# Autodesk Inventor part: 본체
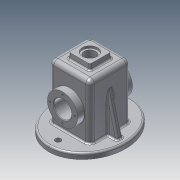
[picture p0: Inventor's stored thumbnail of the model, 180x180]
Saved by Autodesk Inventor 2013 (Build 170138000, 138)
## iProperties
Created: 2017-07
Part Number: 본체
Material: 알루미늄 6061
Document SubType Name: Modeling
Designer: Administrator
Density: 1 g/cm^3
Author: Administrator
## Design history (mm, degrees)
sketch "스케치1"
  geometry: L1 (-37, -55)-(37, -55); L2 (37, -55)-(37, 55); L3 (37, 55)-(-37, 55); L4 (-37, 55)-(-37, -55); L5 (-37, -55)-(37, 55); L6 (37, -55)-(-37, 55); 3 further points
  constraints: 12 end point, 3 midpoint, 2 parallel, 1 coincident, 1 horizontal, 1 perpendicular
  dimensions: "d0" = 74 distance of L3.end L2.end; "d1" = 110 distance of L2.end L1.end
extrude "돌출1" new body sketch "스케치1" stored distance "d2" = 74; taper "d3" = 0 deg
fillet "모깎기1" dims "d4" = 8
fillet "모깎기2" dims "d5" = 8
feature "쉘1" dims "d6" = 5
sketch "스케치2"
  geometry: L1 (-55, 32)-(47, 32) reference; L2 (-55, -29)-(-55, 29) reference; L3 (-55, 29)-(-55, 32) reference; L4 (-55, 37)-(47, 37) reference; L5 (-55, 0)-(0, 0); L6 (0, 0)-(0, 37); L7 (34.5, 32)-(27.5, 25); L8 (27.5, 25)-(0, 25); L9 (0, 32)-(34.5, 32); L10 (0, 32)-(0, 25); A1 r 8 centre (47, 29) between (55, 29) and (47, 37) reference; 1 further point
  constraints: 12 end point, 5 point on line, 2 perpendicular, 1 collinear, 1 midpoint, 1 parallel
  dimensions: "d10" = 55 distance of L5.start L5.end; "d11" = 7 distance between parallel lines of L8 L9; "d12" = 135 deg angle of L8 L7; "d13" = 55 diameter of L7.end L6
revolve "회전1" sketch "스케치2" stored, may be unused: angle "d14" = 90 deg
fillet "모깎기5" dims "d45" = 0.5
sketch "스케치7"
  geometry: C1 r 27.5 at (0, 0); 1 further point
  constraints: 1 centre point, 1 coincident
  dimensions: "d46" = 55 diameter of C1
extrude "돌출5" join sketch "스케치7" distance "d47" = 13; taper "d48" = 0 deg
sketch "스케치8"
  geometry: C1 r 27.5 at (0, 0) reference; C2 r 16 at (0, 0)
  constraints: 1 centre point, 1 coincident
  dimensions: "d49" = 32 diameter of C2
extrude "돌출6" cut sketch "스케치8" stored distance "d50" = 13; taper "d51" = 0 deg
fillet "모깎기6" dims "d52" = 0.5
sketch "스케치9"
  geometry: L1 (0, 0)-(0, 22.5); C1 r 27.5 at (0, 0) reference; 1 further point
  constraints: 2 end point, 1 coincident, 1 vertical
  dimensions: "d53" = 22.5 distance of L1.start L1.end
hole "구멍2" sketch "스케치9" at (0, 22.5) diameter "d54" = 3.242; stored, may be unused: countersink angle "d58" = 90 deg, drill point angle "d60" = 118 deg; dims "d55" = 8, "d56" = 4, "d57" = 2, "d59" = 10
node "작업 평면2"
sketch "스케치10" dims "d67" = 65, "d68" = 75
  geometry: L1 (-65, 75)-(65, 75); L2 (65, 75)-(65, -75); L3 (65, -75)-(-65, -75); L4 (-65, -75)-(-65, 75); L5 (-65, 75)-(65, -75); L6 (65, 75)-(-65, -75); L7 (-32, 29)-(-32, -29) reference; L8 (29, 32)-(-29, 32) reference; L9 (32, -29)-(32, 29) reference; L10 (29, 32)-(-29, 32) reference; L11 (-32, 29)-(-32, -29) reference; L12 (-29, -32)-(29, -32) reference; L13 (-29, -37)-(29, -37) reference; L14 (-37, -29)-(-37, 29) reference; L15 (29, 37)-(-29, 37) reference; L16 (37, 29)-(37, -29) reference; A1 r 3 centre (-29, 29) between (-29, 32) and (-32, 29) reference; A2 r 3 centre (29, -29) between (29, -32) and (32, -29) reference; A3 r 3 centre (29, 29) between (32, 29) and (29, 32) reference; A4 r 3 centre (-29, 29) between (-29, 32) and (-32, 29) reference; A5 r 3 centre (-29, -29) between (-32, -29) and (-29, -32) reference; A6 r 8 centre (29, -29) between (29, -37) and (37, -29) reference; A7 r 8 centre (-29, -29) between (-37, -29) and (-29, -37) reference; A8 r 8 centre (-29, 29) between (-29, 37) and (-37, 29) reference; A9 r 8 centre (29, 29) between (37, 29) and (29, 37) reference; 4 further points; 1 other entity
  constraints: 12 end point, 3 midpoint, 2 coincident, 2 parallel, 1 horizontal, 1 perpendicular, 1 vertical, 2 other
  dimensions: "d65" = 130 distance of L2.end L3.end; "d66" = 150 distance of L1.end L2.end
extrude "돌출7" join sketch "스케치10" distance "d69" = 10; taper "d70" = 0 deg
sketch "스케치11"
  geometry: C1 r 27.5 at (0, 0); 1 further point
  constraints: 1 centre point, 1 coincident
  dimensions: "d71" = 55 diameter of C1
extrude "돌출8" join sketch "스케치11" distance "d72" = 13; taper "d73" = 0 deg
sketch "스케치12"
  geometry: C1 r 27.5 at (0, 0) reference; C2 r 16 at (0, 0)
  constraints: 1 centre point, 1 coincident
  dimensions: "d74" = 32 diameter of C2
extrude "돌출9" cut sketch "스케치12" stored distance "d75" = 13; taper "d76" = 0 deg
sketch "스케치13"
  geometry: L1 (0, 0)-(0, 22.5); C1 r 16 at (0, 0) reference; 1 further point
  constraints: 2 coincident, 2 end point, 1 vertical
  dimensions: "d77" = 22.5 distance of L1.start L1.end
hole "구멍3" sketch "스케치13" at (0, 22.5) diameter "d78" = 3.242; stored, may be unused: countersink angle "d82" = 90 deg, drill point angle "d84" = 118 deg; dims "d79" = 8, "d80" = 4, "d81" = 2, "d83" = 10
chamfer "모따기2" distance "d88" = 1; stored, may be unused: second distance "d89" = 2, angle "d90" = 45 deg
fillet "모깎기7" dims "d91" = 0.5
sketch "스케치14"
  geometry: L1 (65, -45)-(-65, -45) reference; L2 (-65, -55)-(65, -55) reference; L3 (-37, -45)-(-37, 47) reference; L4 (-65, -45)-(-55, -45); L5 (-55, -45)-(-37, 27.194); L6 (-29, 55)-(29, 55) reference; L7 (37, 47)-(37, -45) reference; L8 (37, -45)-(65, -45) reference; L9 (65, -45)-(65, -55) reference; L10 (65, -55)-(32, -55) reference; L11 (32, -55)-(32, 47) reference; L12 (29, 50)-(-29, 50) reference; L13 (-32, 47)-(-32, -55) reference; L14 (-32, -55)-(-65, -55) reference; L15 (-65, -55)-(-65, -45) reference; L16 (-65, -45)-(-37, -45) reference; L17 (-37, -45)-(-37, 47) reference; A1 r 8 centre (-29, 47) between (-29, 55) and (-37, 47) reference; A2 r 8 centre (29, 47) between (37, 47) and (29, 55) reference; A3 r 3 centre (29, 47) between (32, 47) and (29, 50) reference; A4 r 3 centre (-29, 47) between (-29, 50) and (-32, 47) reference; 1 further point
  constraints: 4 end point, 2 point on line
  dimensions: "d92" = 10 distance of L1.end L4.end; "d93" = 14 deg angle of L5 L15
feature "리브1" sketch "스케치14" dims "d94" = 1, "d95" = 10, "d96" = 0, "d97" = 0, "d98" = 1, "d99" = 1
fillet "모깎기8" dims "d100" = 3
fillet "모깎기9" dims "d101" = 3
fillet "모깎기10" dims "d102" = 3
fillet "모깎기11" dims "d103" = 3
fillet "모깎기12" dims "d104" = 3
fillet "모깎기13" dims "d105" = 3
sketch "스케치15"
  geometry: L1 (-40, -8)-(-40, -29) reference; L2 (0, 0)-(0, -58); C1 r 5 at (0, -58); 2 further points
  constraints: 2 coincident, 2 end point, 1 centre point, 1 parallel
  dimensions: "d106" = 58 distance of L2.start L2.end; "d107" = 10 diameter of C1
extrude "돌출10" cut sketch "스케치15" stored distance "d108" = 13; taper "d109" = 0 deg
sketch "스케치16"
  geometry: L1 (9, -49)-(49, -49); L2 (49, -49)-(49, -9); L3 (49, -9)-(9, -9); L4 (9, -9)-(9, -49); L5 (9, -49)-(49, -9); L6 (49, -49)-(9, -9); 3 further points
  constraints: 12 end point, 3 midpoint, 2 parallel, 1 coincident, 1 horizontal, 1 perpendicular
  dimensions: "d110" = 40 distance of L3.end L2.end; "d111" = 40 distance of L2.end L1.end
extrude "돌출11" join sketch "스케치16" distance "d112" = 10; taper "d113" = -5 deg
fillet "모깎기14" dims "d121" = 3
fillet "모깎기15" dims "d122" = 3
chamfer "모따기3" distance "d123" = 1; stored, may be unused: second distance "d124" = 2, angle "d125" = 45 deg
sketch "스케치18"
  geometry: L1 (56.54, -48)-(56.54, -55) reference; L2 (56.54, -55)-(-56.54, -55) reference; L3 (-56.54, -55)-(-56.54, -48) reference; L4 (-53.181, -45)-(-36.55, -45) reference; L5 (29, -42)-(-29, -42) reference; L6 (36.55, -45)-(53.181, -45) reference; L7 (-29, 47)-(-29, -42) reference; L8 (29, 47)-(-29, 47) reference; L9 (29, -42)-(29, 47) reference; L10 (16.137, 65)-(-16.137, 65) reference; L11 (37, -42)-(37, 47) reference; C1 r 16 at (0, 0) reference; C2 r 28 at (0, 0) reference; 1 further point
  constraints: 5 other
  dimensions: "d126" = 30 distance from line of point (0, 35) L10; "d127" = 37 distance from line of L11 point (0, 35)
feature "엠보싱1" sketch "스케치18" dims "d128" = 0.5, "d129" = 0
sketch "스케치19"
  geometry: C1 r 14 at (29, -29); 1 further point
  constraints: 1 centre point, 1 coincident
  dimensions: "d130" = 28 diameter of C1
extrude "돌출12" cut sketch "스케치19" distance "d131" = 4; taper "d132" = 0 deg
sketch "스케치20"
  geometry: C1 r 14 at (0, 0) reference; C2 r 10.5 at (0, 0)
  constraints: 1 centre point, 1 coincident
  dimensions: "d133" = 21 diameter of C2
extrude "돌출13" cut sketch "스케치20" stored distance "d134" = 4; taper "d135" = 0 deg
node "솔리드1"
mirror "대칭1"
pattern_circular "원형 패턴2" dims angle "d62" = 360 deg
pattern_circular "원형 패턴3" dims angle "d86" = 360 deg
mirror "대칭2"
mirror "대칭3"
node "투영된 루프1"
node "투영된 루프2"
node "절단 모서리 투영1"
node "절단 모서리 투영2"
other parameters: "d64" = -55
